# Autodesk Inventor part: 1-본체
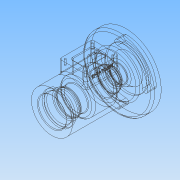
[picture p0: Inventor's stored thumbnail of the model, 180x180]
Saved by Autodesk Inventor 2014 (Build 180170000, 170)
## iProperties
Created: 2017-05
Part Number: 1-본체
Material: Generic
Document SubType Name: Modeling
Designer: user
Density: 1 g/cm^3
Appearance: Default
Author: user
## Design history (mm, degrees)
sketch "Sketch2"
  geometry: L1 (0, 0)-(115, 0); L2 (0, 0)-(0, 31); L3 (0, 31)-(99, 31); L4 (99, 31)-(99, 53); L5 (99, 53)-(112, 53); L6 (112, 53)-(112, 31); L7 (112, 31)-(115, 31); L8 (115, 31)-(115, 0)
  constraints: 16 end point, 4 parallel, 2 collinear, 2 perpendicular, 1 horizontal
  dimensions: "d0" = 115 distance of L1.start L1.end; "d1" = 3 distance between parallel lines of L8 L6; "d2" = 13 distance of L4.end L5.end; "d3" = 106 diameter of L5 L1; "d4" = 62 diameter of L3 L1
revolve "Revolution1" sketch "Sketch2" stored, may be unused: angle "d5" = 90 deg
workplane "Work Plane1"
sketch "Sketch3"
  geometry: L1 (-81, -20)-(-31, -20); L2 (-31, -20)-(-31, 20); L3 (-31, 20)-(-81, 20); L4 (-81, 20)-(-81, -20); L5 (-81, -20)-(-31, 20); L6 (-31, -20)-(-81, 20); L7 (0, 31)-(0, -31) reference; 4 further points
  constraints: 12 end point, 4 midpoint, 2 parallel, 1 horizontal, 1 horizontal alignment, 1 perpendicular
  dimensions: "d7" = 56 distance from line of L7 point (-56, 0); "d8" = 40 distance of L1.end L2.end; "d9" = 50 distance of L1.start L1.end
extrude "Extrusion1" join sketch "Sketch3" stored distance "d10" = 10; taper "d11" = 0 deg
sketch "Sketch4"
  geometry: L1 (0, -31)-(0, 31) reference; L2 (115, -31)-(115, 31) reference; L3 (0, 0)-(115, 0); L4 (0, 21)-(9, 21); L5 (9, 21)-(9, 24); L6 (9, 24)-(12, 24); L7 (12, 24)-(12, 20); L8 (21, 20)-(21, 17.5); L9 (21, 17.5)-(24.25, 17.5); L10 (24.25, 17.5)-(24.25, 18.5); L11 (24.25, 18.5)-(26, 18.5); L12 (26, 18.5)-(26, 17.5); L13 (26, 17.5)-(37, 17.5); L14 (37, 17.5)-(37, 26); L15 (37, 26)-(75, 26); L16 (75, 26)-(75, 17.5); L17 (75, 17.5)-(86, 17.5); L18 (86, 17.5)-(86, 16.5); L19 (86, 16.5)-(91, 16.5); L20 (91, 16.5)-(91, 10); L21 (91, 10)-(93.7, 10); L22 (93.7, 10)-(93.7, 12.5); L23 (93.7, 12.5)-(100.3, 12.5); L24 (100.3, 12.5)-(101, 12.904); L25 (101, 12.904)-(101, 16); L26 (101, 16)-(115, 22); L27 (12, 20)-(21, 20)
  constraints: 50 end point, 15 parallel, 6 perpendicular, 2 collinear, 2 point on line, 1 midpoint, 1 vertical
  dimensions: "d12" = 42 diameter of L4 L3; "d17" = 3 distance of L5.end L6.end; "d18" = 12 distance between parallel lines of L7 L1; "d19" = 21 distance between parallel lines of L8 L1; "d20" = 26 distance between parallel lines of L12 L1; "d21" = 1.75 distance of L10.end L11.end; "d22" = 38 distance of L14.end L15.end; "d23" = 86 distance between parallel lines of L18 L1; "d24" = 5 distance between parallel lines of L20 L18; "d25" = 14 distance between parallel lines of L25 L2; "d26" = 0.7 horizontal distance of L24.end L23.end; "d27" = 30 deg angle of L23 L24; "d28" = 48 diameter of L6 L3; "d29" = 37 diameter of L11 L3; "d30" = 35 diameter of L9 L3; "d32" = 32 diameter of L25.end L3; "d33" = 44 diameter of L26.end L3; "d34" = 7.3 distance from line of L22 L24.end; "d35" = 20 diameter of L21 L3; "d36" = 25 diameter of L23 L3; "d37" = 33 diameter of L19 L3; "d38" = 52 diameter of L15 L3; "d39" = 11 distance between parallel lines of L12 L14; "d85" = 40 diameter of L27 L3
revolve "Revolution2" sketch "Sketch4" stored, may be unused: angle "d40" = 90 deg
sketch "Sketch5"
  geometry: L1 (-40, -11)-(-72, -11); L2 (-72, -11)-(-72, 11); L3 (-72, 11)-(-40, 11); L4 (-40, 11)-(-40, -11); L5 (-40, -11)-(-72, 11); L6 (-72, -11)-(-40, 11); L7 (-115, 31)-(-115, -31) reference; L8 (0, 31)-(0, -31) reference; 3 further points
  constraints: 12 end point, 3 midpoint, 2 parallel, 1 horizontal, 1 horizontal alignment, 1 perpendicular
  dimensions: "d42" = 32 distance of L2.end L3.end; "d43" = 22 distance of L3.end L1.start; "d44" = 56 distance from line of L8 point (-56, 0)
extrude "Extrusion2" cut sketch "Sketch5" stored distance "d45" = 10; taper "d46" = 0 deg
sketch "Sketch6"
  geometry: L1 (-81, 20)-(-81, -20) reference; L2 (-35.5, -15.5)-(-76.5, -15.5); L3 (-76.5, -15.5)-(-76.5, 15.5); L4 (-76.5, 15.5)-(-35.5, 15.5); L5 (-35.5, 15.5)-(-35.5, -15.5); L6 (-35.5, -15.5)-(-76.5, 15.5); L7 (-76.5, -15.5)-(-35.5, 15.5); L8 (0, 31)-(0, -31) reference; 4 further points
  constraints: 12 end point, 4 midpoint, 2 parallel, 1 horizontal, 1 horizontal alignment, 1 perpendicular
  dimensions: "d47" = 56 distance from line of L8 point (-56, 0); "d48" = 41 distance of L3.end L4.end; "d49" = 31 distance of L4.end L2.start
hole "Hole1" sketch "Sketch6" at (-35.5, 15.5), (-35.5, -15.5), (-76.5, -15.5), (-76.5, 15.5) diameter "d50" = 2.459; stored, may be unused: countersink angle "d54" = 90 deg, drill point angle "d56" = 118 deg; dims "d51" = 6, "d52" = 4, "d53" = 2, "d55" = 8
fillet "Fillet1" dims "d57" = 3
fillet "Fillet2" dims "d58" = 1
fillet "Fillet3" dims "d59" = 3
fillet "Fillet4" dims "d60" = 3
thread "Thread1" dims "d61" = 10, "d62" = 0
chamfer "Chamfer1" distance "d63" = 1; stored, may be unused: second distance "d64" = 2, angle "d65" = 45 deg
sketch "Sketch7"
  geometry: L1 (0, 0)-(45.5, 0); L2 (0, 0)-(0, -45.5); L3 (0, 0)-(-45.5, 0); L4 (0, 0)-(0, 45.5); C1 r 31 at (0, 0) reference; A1 r 41.5 centre (0, 0) between (0, -41.5) and (41.5, 0); A2 r 4 centre (0, -41.5) between (0, -45.5) and (0, -37.5); A3 r 4 centre (41.5, 0) between (37.5, 0) and (45.5, 0); A4 r 4 centre (0, 41.5) between (0, 45.5) and (0, 37.5); A5 r 4 centre (-41.5, 0) between (-37.5, 0) and (-45.5, 0); A6 r 37.5 centre (0, 0) between (-37.5, 0) and (0, -37.5); A7 r 37.5 centre (0, 0) between (37.5, 0) and (0, 37.5); A8 r 45.5 centre (0, 0) between (45.5, 0) and (0, 45.5); A9 r 45.5 centre (0, 0) between (-45.5, 0) and (0, -45.5)
  constraints: 20 point on circle, 9 centre point, 8 end point, 4 point on line, 3 coincident, 3 perpendicular, 2 equal radius, 1 horizontal
  dimensions: "d67" = 83 diameter of A1; "d71" = 4 radius of A5; "d72" = 37.5 radius of A7
extrude "Extrusion3" cut sketch "Sketch7" distance "d73" = 13; taper "d74" = 0 deg
fillet "Fillet5" dims "d75" = 3
fillet "Fillet6" dims "d76" = 0.3
chamfer "Chamfer2" distance "d77" = 1; stored, may be unused: second distance "d78" = 2, angle "d79" = 45 deg
sketch "Sketch8"
  geometry: L1 (44, 0)-(0, 0) reference; L2 (78, 75)-(78, 13) reference; 2 further points
  constraints: 1 other
  dimensions: "d80" = 8 distance from line of point (22, 8) L1; "d81" = 56 distance from line of point (22, 8) L2
emboss "Emboss1" sketch "Sketch8" dims "d82" = 0.5, "d83" = 0
fillet "Fillet7" dims "d84" = 3
body "Solid1"
other parameters: "d6" = 44, "d69" = 75, "d70" = 91
